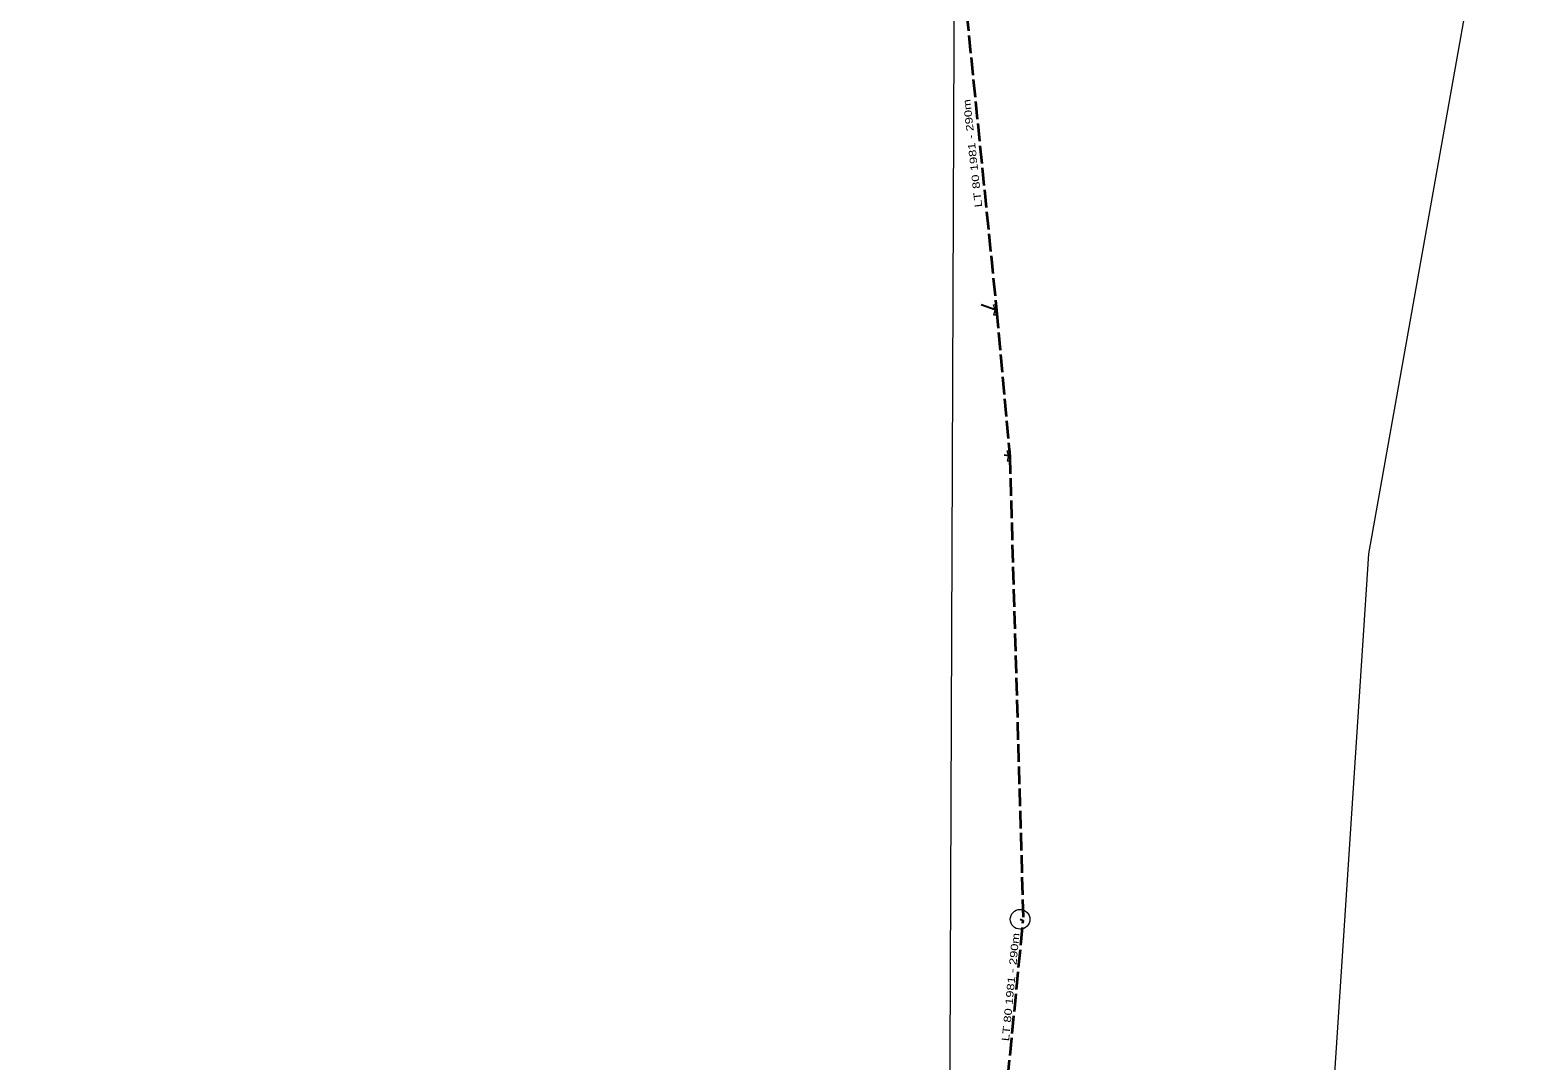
# Model space of a CAD drawing. Extents: x -616592 to -615844, y -1088988 to -1088174.
# Drawn here: x -616410.7 to -616257.7, y -1088735.2 to -1088630.7 of the extents above; entities that cross this region are included whole.
import ezdxf
from ezdxf.enums import TextEntityAlignment as Align

# ---------------------------------------------------------------- set-up
doc = ezdxf.new("R2010")
doc.units = 0
doc.header["$LTSCALE"] = 0.3
doc.linetypes.add('LONG_DASHED', pattern=[7.5, 6, -1.5])
for name, color, linetype, lineweight in [('1', 7, 'Continuous', 13), ('10', 7, 'Continuous', 13), ('35', 7, 'LONG_DASHED', 35), ('50', 7, 'LONG_DASHED', 25)]:
    doc.layers.add(name, color=color, linetype=linetype, lineweight=lineweight)
doc.layers.add('16', color=7, linetype='Continuous')

msp = doc.modelspace()

# ---------------------------------------------------------------- linework, layer by layer
at = {"layer": '1'}
msp.add_lwpolyline([(-616257.711, -1088587.328), (-616274.902, -1088683.788), (-616283.975, -1088822.271), (-616298.779, -1088934.012), (-616386.643, -1088972.214), (-616585.294, -1088987.972), (-616591.502, -1088951.68), (-616447.289, -1088935.922), (-616360.379, -1088913.001), (-616322.655, -1088847.102), (-616317.402, -1088743.479), (-616316.925, -1088623.142)], dxfattribs=at)
at = {"layer": '10'}
for points in [[(-616312.81, -1088659.034), (-616312.96, -1088658.534), (-616312.66, -1088658.534), (-616312.81, -1088659.034), (-616312.96, -1088659.534), (-616312.66, -1088659.534)], [(-616311.432, -1088673.851), (-616311.582, -1088673.351), (-616311.282, -1088673.351), (-616311.432, -1088673.851), (-616311.582, -1088674.351), (-616311.282, -1088674.351)]]:
    msp.add_lwpolyline(points, close=True, dxfattribs=at)
msp.add_circle((-616310.262, -1088720.882), 1, dxfattribs=at)
at = {"layer": '35'}
for p, q in [((-616316.823, -1088617.753), (-616312.654, -1088659.097)), ((-616312.654, -1088659.097), (-616311.317, -1088673.876)), ((-616311.317, -1088673.876), (-616309.946, -1088720.987)), ((-616312.591, -1088748.152), (-616309.946, -1088720.987))]:
    msp.add_line(p, q, dxfattribs=at)
at = {"layer": '50'}
for p, q in [((-616312.81, -1088659.034), (-616314.224, -1088658.523)), ((-616312.654, -1088659.097), (-616312.81, -1088659.034)), ((-616311.432, -1088673.851), (-616311.885, -1088673.798)), ((-616311.317, -1088673.876), (-616311.432, -1088673.851)), ((-616310.262, -1088720.882), (-616309.946, -1088720.987))]:
    msp.add_line(p, q, dxfattribs=at)

# ---------------------------------------------------------------- texts
at = {"layer": '16', "width": 1.3}
for rotation, p in [(96.401, (-616314.7183, -1088643.1078)), (84.439, (-616310.8585, -1088727.7863))]:
    msp.add_text('LT 80 1981 - 290m', height=0.75, rotation=rotation, dxfattribs=at).set_placement(p, align=Align.CENTER)

doc.saveas('drawing.dxf')
